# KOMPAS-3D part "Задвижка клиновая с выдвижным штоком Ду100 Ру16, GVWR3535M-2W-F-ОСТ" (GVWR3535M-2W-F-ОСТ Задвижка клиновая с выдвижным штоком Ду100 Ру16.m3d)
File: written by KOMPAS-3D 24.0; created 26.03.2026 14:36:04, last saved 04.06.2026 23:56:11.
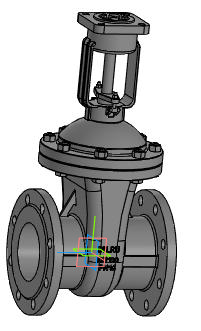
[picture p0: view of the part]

Document properties: Автор: R2D2; Полное имя файла: E:\Работа\Зайцев\GVWR3535M-2W-F-ОСТ Задвижка клиновая 30нж941нж DN.ru Ду50-200 Ру16\исходные данные\DN100\dn100\GVWR3535M-2W-F-ОСТ Задвижка клиновая с выдвижным штоком Ду100 Ру16.m3d

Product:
- Part/product: Задвижка клиновая с выдвижным штоком Ду100 Ру16  | designation GVWR3535M-2W-F-ОСТ
    Масса: 25.5
    Раздел спецификации: Прочие изделия
    Примечание: D040-10557

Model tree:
1. Операция без истории:1

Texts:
  GVWR3535M-2W-F-ОСТ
